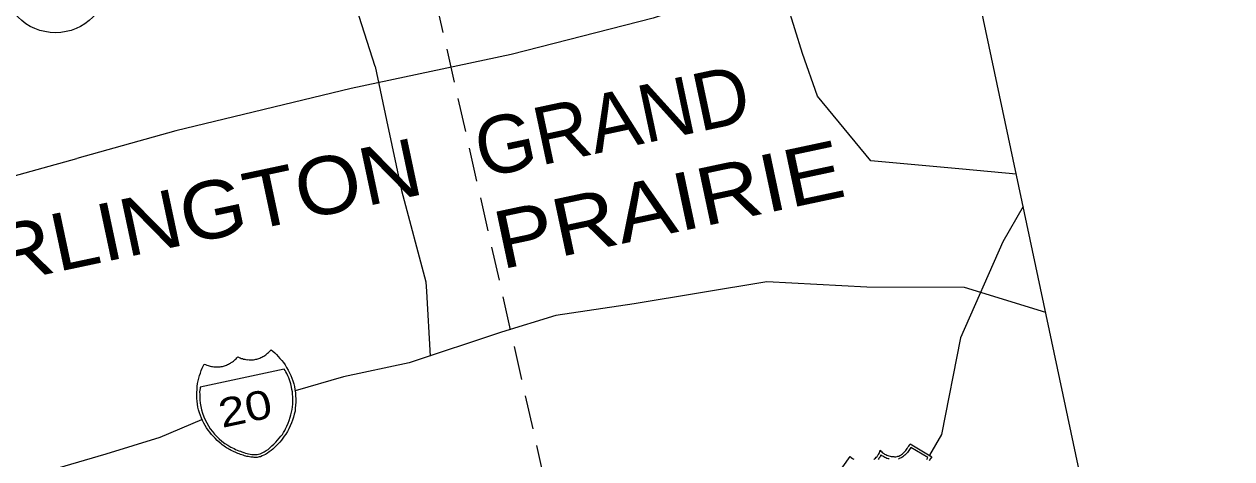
# Model space of a CAD drawing. Extents: x 2357218 to 2371708, y 6973728 to 6980157.
# Drawn here: x 2371493.9 to 2371708, y 6977585.2 to 6977662.2 of the extents above; entities that cross this region are included whole.
import ezdxf

# ---------------------------------------------------------------- set-up
doc = ezdxf.new("R2010")
doc.units = 0
doc.header["$LTSCALE"] = 2
doc.linetypes.add('MEDIUM_DASHED', pattern=[4.5, 3, -1.5])
doc.layers.add('62', color=7, linetype='Continuous', lineweight=13)
doc.layers.add('63', color=7, linetype='Continuous', lineweight=13)

msp = doc.modelspace()

# ---------------------------------------------------------------- linework, layer by layer
at = {"layer": '62', "linetype": 'MEDIUM_DASHED'}
msp.add_line((2371537.006, 6977798.267), (2371599.077, 6977524.204), dxfattribs=at)
at = {"layer": '62'}
for p, q in [((2371556.106, 6977654.73), (2371552.361, 6977666.609)), ((2371565.093, 6977616.567), (2371565.242, 6977614.897)), ((2371565.242, 6977614.897), (2371565.859, 6977603.432)), ((2371656.507, 6977589.526), (2371654.364, 6977585.874))]:
    msp.add_line(p, q, dxfattribs=at)
at = {"layer": '62', "lineweight": 25}
msp.add_line((2371481.196, 6977632.344), (2371503.25, 6977638.459), dxfattribs=at)
for points in [[(2371171.482, 6977817.538), (2371268.218, 6977362.432), (2371707.985, 6977455.907), (2371611.249, 6977911.015)], [(2371659.938, 6977681.952), (2371647.349, 6977677.965), (2371628.369, 6977671.057), (2371605.423, 6977663.305), (2371580.264, 6977656.875), (2371551.849, 6977650.836), (2371520.802, 6977643.338), (2371503.25, 6977638.459)], [(2371674.99, 6977611.147), (2371660.613, 6977615.566), (2371643.295, 6977615.659), (2371625.568, 6977616.583), (2371602.064, 6977612.668), (2371588.144, 6977610.607), (2371578.532, 6977607.666), (2371562.184, 6977602.215), (2371550.54, 6977599.739), (2371541.925, 6977597.309)], [(2371525.33, 6977592.147), (2371517.989, 6977589.024), (2371508.4, 6977586.087), (2371494.884, 6977582.133), (2371485.112, 6977580.058), (2371478.295, 6977577.711), (2371473.995, 6977573.922), (2371464.607, 6977569.925), (2371450.652, 6977568.04), (2371437.897, 6977566.249), (2371423.963, 6977564.162), (2371402.89, 6977556.805), (2371381.813, 6977555.202), (2371364.473, 6977555.496), (2371353.545, 6977558.763), (2371347.781, 6977571.044), (2371345.031, 6977583.983), (2371341.826, 6977589.973), (2371344.749, 6977600.141)]]:
    msp.add_lwpolyline(points, dxfattribs=at)
at = {"layer": '62'}
for points in [[(2371669.776, 6977635.664), (2371660.267, 6977636.565), (2371643.965, 6977638.048), (2371634.547, 6977649.456), (2371631.882, 6977657.01), (2371629.164, 6977665.797), (2371628.025, 6977672.456), (2371627.386, 6977680.002), (2371625.287, 6977686.412), (2371623.525, 6977695.471)], [(2371556.106, 6977654.73), (2371558.125, 6977645.222), (2371560.78, 6977632.741), (2371565.093, 6977616.567)], [(2371670.991, 6977629.94), (2371667.397, 6977623.702), (2371659.911, 6977606.652), (2371656.507, 6977589.526)], [(2371532.597, 6977602.986), (2371532.818, 6977602.918), (2371533.015, 6977602.867), (2371533.203, 6977602.838), (2371533.421, 6977602.793), (2371533.625, 6977602.813), (2371533.797, 6977602.758), (2371534.001, 6977602.777), (2371534.184, 6977602.771), (2371534.391, 6977602.769), (2371534.574, 6977602.786), (2371534.771, 6977602.828), (2371534.969, 6977602.87), (2371535.145, 6977602.907), (2371535.321, 6977602.945), (2371535.514, 6977603.008), (2371535.683, 6977603.09), (2371535.85, 6977603.17), (2371536.043, 6977603.234), (2371536.2, 6977603.359), (2371536.371, 6977603.419), (2371536.55, 6977603.55), (2371536.734, 6977603.658), (2371536.893, 6977603.784), (2371537.044, 6977603.93), (2371537.201, 6977604.056), (2371537.353, 6977604.205), (2371537.546, 6977604.385), (2371537.697, 6977604.53), (2371538.003, 6977604.295), (2371538.337, 6977604.022), (2371538.652, 6977603.722), (2371538.958, 6977603.372), (2371539.261, 6977603.023), (2371539.593, 6977602.654), (2371539.879, 6977602.28), (2371540.177, 6977601.859), (2371540.434, 6977601.408), (2371540.69, 6977600.957), (2371540.952, 6977600.484), (2371541.169, 6977599.999), (2371541.367, 6977599.513), (2371541.532, 6977599.041), (2371541.687, 6977598.546), (2371541.816, 6977598.045), (2371541.909, 6977597.489), (2371541.983, 6977596.928), (2371542.035, 6977596.367), (2371542.075, 6977595.846), (2371542.077, 6977595.294), (2371542.014, 6977594.727), (2371541.967, 6977594.189), (2371541.922, 6977593.65), (2371541.799, 6977593.141), (2371541.639, 6977592.602), (2371541.493, 6977592.088), (2371541.301, 6977591.586), (2371541.092, 6977591.059), (2371540.85, 6977590.571), (2371540.583, 6977590.1), (2371540.274, 6977589.597), (2371540.028, 6977589.244), (2371539.78, 6977588.895), (2371539.512, 6977588.537), (2371539.238, 6977588.203), (2371538.915, 6977587.883), (2371538.596, 6977587.539), (2371538.29, 6977587.243), (2371537.98, 6977586.97), (2371537.672, 6977586.698), (2371537.356, 6977586.447), (2371537.036, 6977586.218), (2371536.684, 6977586.028), (2371536.417, 6977585.878), (2371536.101, 6977585.743), (2371535.829, 6977585.616), (2371535.563, 6977585.559)], [(2371535.563, 6977585.559), (2371535.389, 6977585.522), (2371535.234, 6977585.489), (2371535.029, 6977585.493), (2371534.868, 6977585.481), (2371534.706, 6977585.492), (2371534.493, 6977585.515), (2371534.285, 6977585.519), (2371534.074, 6977585.542), (2371533.858, 6977585.588), (2371533.639, 6977585.634), (2371533.402, 6977585.674), (2371533.207, 6977585.726), (2371532.962, 6977585.789), (2371532.739, 6977585.857), (2371532.521, 6977585.924), (2371532.276, 6977585.987), (2371532.046, 6977586.1), (2371531.796, 6977586.186), (2371531.549, 6977586.27), (2371531.339, 6977586.385), (2371531.113, 6977586.476), (2371530.88, 6977586.61), (2371530.631, 6977586.694), (2371530.443, 6977586.818), (2371530.213, 6977586.93), (2371530.002, 6977587.045), (2371529.769, 6977587.18), (2371529.58, 6977587.323), (2371529.364, 6977587.461), (2371529.177, 6977587.583), (2371529.015, 6977587.711), (2371528.814, 6977587.874), (2371528.456, 6977588.166), (2371528.107, 6977588.505), (2371527.757, 6977588.867), (2371527.454, 6977589.196), (2371527.122, 6977589.562), (2371526.81, 6977589.955), (2371526.522, 6977590.329), (2371526.252, 6977590.734), (2371526.004, 6977591.14), (2371525.753, 6977591.571), (2371525.543, 6977592.009), (2371525.335, 6977592.449), (2371525.144, 6977592.913), (2371524.998, 6977593.388), (2371524.839, 6977593.906), (2371524.712, 6977594.409), (2371524.647, 6977594.924), (2371524.585, 6977595.44), (2371524.527, 6977595.933), (2371524.529, 6977596.463), (2371524.533, 6977596.994), (2371524.554, 6977597.526), (2371524.606, 6977598.044), (2371524.658, 6977598.56), (2371524.757, 6977599.065), (2371524.866, 6977599.524), (2371524.998, 6977599.991), (2371525.156, 6977600.438), (2371525.312, 6977600.886), (2371525.461, 6977601.285), (2371525.655, 6977601.67), (2371525.836, 6977602.008), (2371526.057, 6977601.941), (2371526.285, 6977601.852), (2371526.504, 6977601.782), (2371526.679, 6977601.728), (2371526.898, 6977601.658), (2371527.093, 6977601.608), (2371527.304, 6977601.585), (2371527.523, 6977601.54), (2371527.704, 6977601.554), (2371527.898, 6977601.504), (2371528.102, 6977601.525), (2371528.286, 6977601.518), (2371528.491, 6977601.515), (2371528.674, 6977601.532), (2371528.852, 6977601.57), (2371529.071, 6977601.614), (2371529.223, 6977601.649), (2371529.423, 6977601.689), (2371529.595, 6977601.748), (2371529.783, 6977601.836), (2371529.952, 6977601.916), (2371530.123, 6977601.977), (2371530.302, 6977602.106), (2371530.492, 6977602.171), (2371530.628, 6977602.292), (2371530.814, 6977602.399), (2371530.993, 6977602.529), (2371531.169, 6977602.683), (2371531.303, 6977602.803), (2371531.477, 6977602.954), (2371531.625, 6977603.123), (2371531.801, 6977603.277), (2371531.999, 6977603.204), (2371532.179, 6977603.103), (2371532.404, 6977603.037), (2371532.597, 6977602.986)], [(2371644.497, 6977585.11), (2371644.654, 6977585.234), (2371644.812, 6977585.36), (2371644.96, 6977585.529), (2371645.091, 6977585.672), (2371645.212, 6977585.861), (2371645.346, 6977585.981), (2371645.442, 6977586.186), (2371645.519, 6977586.363), (2371645.569, 6977586.557), (2371645.62, 6977586.753), (2371645.767, 6977586.599), (2371645.939, 6977586.452), (2371646.084, 6977586.299), (2371646.271, 6977586.178), (2371646.435, 6977586.051), (2371646.635, 6977585.977), (2371646.818, 6977585.878), (2371647.017, 6977585.807), (2371647.212, 6977585.754), (2371647.411, 6977585.682), (2371647.623, 6977585.658), (2371647.813, 6977585.63), (2371648.043, 6977585.635), (2371648.212, 6977585.599), (2371648.441, 6977585.603), (2371648.638, 6977585.645), (2371648.793, 6977585.677), (2371648.969, 6977585.715), (2371649.107, 6977585.813), (2371649.298, 6977585.899), (2371649.433, 6977586.02), (2371649.595, 6977586.125), (2371649.727, 6977586.266), (2371649.884, 6977586.392), (2371650.01, 6977586.557), (2371650.18, 6977586.731), (2371650.305, 6977586.895), (2371650.454, 6977587.065), (2371650.57, 6977587.274), (2371650.734, 6977587.471), (2371650.832, 6977587.676), (2371650.969, 6977587.888), (2371654.786, 6977585.616), (2371654.561, 6977585.273), (2371654.346, 6977584.881)], [(2371653.923, 6977585.136), (2371654.08, 6977585.468), (2371651.078, 6977587.267), (2371650.956, 6977587.082), (2371650.856, 6977586.897), (2371650.741, 6977586.689), (2371650.616, 6977586.525), (2371650.467, 6977586.354), (2371650.318, 6977586.187), (2371650.168, 6977586.038), (2371650.013, 6977585.892), (2371649.834, 6977585.762), (2371649.681, 6977585.615), (2371649.5, 6977585.484), (2371649.357, 6977585.407), (2371649.169, 6977585.322), (2371649.019, 6977585.266), (2371648.895, 6977585.194)], [(2371637.751, 6977581.997), (2371640.317, 6977585.624), (2371640.535, 6977585.464), (2371640.753, 6977585.302), (2371640.983, 6977585.191)], [(2371647.236, 6977585.21), (2371647.067, 6977585.243), (2371646.825, 6977585.306), (2371646.669, 6977585.387), (2371646.492, 6977585.466), (2371646.289, 6977585.558), (2371646.144, 6977585.689), (2371645.964, 6977585.79), (2371645.79, 6977585.96), (2371645.695, 6977585.756), (2371645.618, 6977585.577), (2371645.491, 6977585.413), (2371645.382, 6977585.275), (2371645.272, 6977585.136)]]:
    msp.add_lwpolyline(points, dxfattribs=at)
msp.add_lwpolyline([(2371540.018, 6977601.089), (2371525.116, 6977597.923), (2371525.097, 6977597.687), (2371525.041, 6977597.4), (2371525.018, 6977597.074), (2371525.043, 6977596.642), (2371525.022, 6977596.2), (2371525.042, 6977595.676), (2371525.114, 6977595.115), (2371525.219, 6977594.516), (2371525.371, 6977593.904), (2371525.545, 6977593.298), (2371525.764, 6977592.701), (2371525.997, 6977592.152), (2371526.276, 6977591.59), (2371526.569, 6977591.078), (2371526.912, 6977590.552), (2371527.267, 6977590.076), (2371527.64, 6977589.627), (2371528.062, 6977589.162), (2371528.493, 6977588.748), (2371528.972, 6977588.346), (2371529.487, 6977587.97), (2371529.992, 6977587.642), (2371530.545, 6977587.322), (2371531.108, 6977587.049), (2371531.375, 6977586.877), (2371531.67, 6977586.778), (2371531.95, 6977586.655), (2371532.27, 6977586.562), (2371532.523, 6977586.452), (2371532.824, 6977586.335), (2371533.118, 6977586.259), (2371533.43, 6977586.187), (2371533.696, 6977586.129), (2371533.983, 6977586.075), (2371534.273, 6977586.021), (2371534.506, 6977586.001), (2371534.76, 6977585.988), (2371534.991, 6977585.989), (2371535.243, 6977585.998), (2371535.462, 6977586.043), (2371535.766, 6977586.132), (2371536.126, 6977586.278), (2371536.429, 6977586.479), (2371536.817, 6977586.701), (2371537.167, 6977586.912), (2371537.493, 6977587.213), (2371537.842, 6977587.516), (2371538.188, 6977587.841), (2371538.527, 6977588.191), (2371538.825, 6977588.53), (2371539.119, 6977588.869), (2371539.41, 6977589.228), (2371539.685, 6977589.562), (2371539.888, 6977589.906), (2371540.098, 6977590.226), (2371540.237, 6977590.533), (2371540.474, 6977591.043), (2371540.683, 6977591.571), (2371540.882, 6977592.05), (2371541.043, 6977592.59), (2371541.173, 6977593.055), (2371541.282, 6977593.515), (2371541.393, 6977593.975), (2371541.452, 6977594.448), (2371541.512, 6977594.923), (2371541.561, 6977595.347), (2371541.556, 6977595.805), (2371541.532, 6977596.235), (2371541.488, 6977596.663), (2371541.465, 6977597.096), (2371541.377, 6977597.513), (2371541.309, 6977597.936), (2371541.161, 6977598.526), (2371541.001, 6977599.068), (2371540.825, 6977599.559), (2371540.672, 6977599.964), (2371540.472, 6977600.357), (2371540.296, 6977600.643), (2371540.152, 6977600.887)], close=True, dxfattribs=at)
msp.add_circle((2371499.456, 6977670.084), 9.364, dxfattribs=at)
at = {"layer": '63', "linetype": 'MEDIUM_DASHED'}
msp.add_line((2371537.006, 6977798.267), (2371599.077, 6977524.204), dxfattribs=at)
at = {"layer": '63'}
for p, q in [((2371556.106, 6977654.73), (2371552.361, 6977666.609)), ((2371565.093, 6977616.567), (2371565.242, 6977614.897)), ((2371565.242, 6977614.897), (2371565.859, 6977603.432)), ((2371656.507, 6977589.526), (2371654.364, 6977585.874))]:
    msp.add_line(p, q, dxfattribs=at)
at = {"layer": '63', "lineweight": 25}
msp.add_line((2371481.196, 6977632.344), (2371503.25, 6977638.459), dxfattribs=at)
for points in [[(2371171.482, 6977817.538), (2371268.218, 6977362.432), (2371707.985, 6977455.907), (2371611.249, 6977911.015)], [(2371659.938, 6977681.952), (2371647.349, 6977677.965), (2371628.369, 6977671.057), (2371605.423, 6977663.305), (2371580.264, 6977656.875), (2371551.849, 6977650.836), (2371520.802, 6977643.338), (2371503.25, 6977638.459)], [(2371674.99, 6977611.147), (2371660.613, 6977615.566), (2371643.295, 6977615.659), (2371625.568, 6977616.583), (2371602.064, 6977612.668), (2371588.144, 6977610.607), (2371578.532, 6977607.666), (2371562.184, 6977602.215), (2371550.54, 6977599.739), (2371541.925, 6977597.309)], [(2371525.33, 6977592.147), (2371517.989, 6977589.024), (2371508.4, 6977586.087), (2371494.884, 6977582.133), (2371485.112, 6977580.058), (2371478.295, 6977577.711), (2371473.995, 6977573.922), (2371464.607, 6977569.925), (2371450.652, 6977568.04), (2371437.897, 6977566.249), (2371423.963, 6977564.162), (2371402.89, 6977556.805), (2371381.813, 6977555.202), (2371364.473, 6977555.496), (2371353.545, 6977558.763), (2371347.781, 6977571.044), (2371345.031, 6977583.983), (2371341.826, 6977589.973), (2371344.749, 6977600.141)]]:
    msp.add_lwpolyline(points, dxfattribs=at)
at = {"layer": '63'}
for points in [[(2371669.776, 6977635.664), (2371660.267, 6977636.565), (2371643.965, 6977638.048), (2371634.547, 6977649.456), (2371631.882, 6977657.01), (2371629.164, 6977665.797), (2371628.025, 6977672.456), (2371627.386, 6977680.002), (2371625.287, 6977686.412), (2371623.525, 6977695.471)], [(2371556.106, 6977654.73), (2371558.125, 6977645.222), (2371560.78, 6977632.741), (2371565.093, 6977616.567)], [(2371670.991, 6977629.94), (2371667.397, 6977623.702), (2371659.911, 6977606.652), (2371656.507, 6977589.526)], [(2371532.597, 6977602.986), (2371532.818, 6977602.918), (2371533.015, 6977602.867), (2371533.203, 6977602.838), (2371533.421, 6977602.793), (2371533.625, 6977602.813), (2371533.797, 6977602.758), (2371534.001, 6977602.777), (2371534.184, 6977602.771), (2371534.391, 6977602.769), (2371534.574, 6977602.786), (2371534.771, 6977602.828), (2371534.969, 6977602.87), (2371535.145, 6977602.907), (2371535.321, 6977602.945), (2371535.514, 6977603.008), (2371535.683, 6977603.09), (2371535.85, 6977603.17), (2371536.043, 6977603.234), (2371536.2, 6977603.359), (2371536.371, 6977603.419), (2371536.55, 6977603.55), (2371536.734, 6977603.658), (2371536.893, 6977603.784), (2371537.044, 6977603.93), (2371537.201, 6977604.056), (2371537.353, 6977604.205), (2371537.546, 6977604.385), (2371537.697, 6977604.53), (2371538.003, 6977604.295), (2371538.337, 6977604.022), (2371538.652, 6977603.722), (2371538.958, 6977603.372), (2371539.261, 6977603.023), (2371539.593, 6977602.654), (2371539.879, 6977602.28), (2371540.177, 6977601.859), (2371540.434, 6977601.408), (2371540.69, 6977600.957), (2371540.952, 6977600.484), (2371541.169, 6977599.999), (2371541.367, 6977599.513), (2371541.532, 6977599.041), (2371541.687, 6977598.546), (2371541.816, 6977598.045), (2371541.909, 6977597.489), (2371541.983, 6977596.928), (2371542.035, 6977596.367), (2371542.075, 6977595.846), (2371542.077, 6977595.294), (2371542.014, 6977594.727), (2371541.967, 6977594.189), (2371541.922, 6977593.65), (2371541.799, 6977593.141), (2371541.639, 6977592.602), (2371541.493, 6977592.088), (2371541.301, 6977591.586), (2371541.092, 6977591.059), (2371540.85, 6977590.571), (2371540.583, 6977590.1), (2371540.274, 6977589.597), (2371540.028, 6977589.244), (2371539.78, 6977588.895), (2371539.512, 6977588.537), (2371539.238, 6977588.203), (2371538.915, 6977587.883), (2371538.596, 6977587.539), (2371538.29, 6977587.243), (2371537.98, 6977586.97), (2371537.672, 6977586.698), (2371537.356, 6977586.447), (2371537.036, 6977586.218), (2371536.684, 6977586.028), (2371536.417, 6977585.878), (2371536.101, 6977585.743), (2371535.829, 6977585.616), (2371535.563, 6977585.559)], [(2371535.563, 6977585.559), (2371535.389, 6977585.522), (2371535.234, 6977585.489), (2371535.029, 6977585.493), (2371534.868, 6977585.481), (2371534.706, 6977585.492), (2371534.493, 6977585.515), (2371534.285, 6977585.519), (2371534.074, 6977585.542), (2371533.858, 6977585.588), (2371533.639, 6977585.634), (2371533.402, 6977585.674), (2371533.207, 6977585.726), (2371532.962, 6977585.789), (2371532.739, 6977585.857), (2371532.521, 6977585.924), (2371532.276, 6977585.987), (2371532.046, 6977586.1), (2371531.796, 6977586.186), (2371531.549, 6977586.27), (2371531.339, 6977586.385), (2371531.113, 6977586.476), (2371530.88, 6977586.61), (2371530.631, 6977586.694), (2371530.443, 6977586.818), (2371530.213, 6977586.93), (2371530.002, 6977587.045), (2371529.769, 6977587.18), (2371529.58, 6977587.323), (2371529.364, 6977587.461), (2371529.177, 6977587.583), (2371529.015, 6977587.711), (2371528.814, 6977587.874), (2371528.456, 6977588.166), (2371528.107, 6977588.505), (2371527.757, 6977588.867), (2371527.454, 6977589.196), (2371527.122, 6977589.562), (2371526.81, 6977589.955), (2371526.522, 6977590.329), (2371526.252, 6977590.734), (2371526.004, 6977591.14), (2371525.753, 6977591.571), (2371525.543, 6977592.009), (2371525.335, 6977592.449), (2371525.144, 6977592.913), (2371524.998, 6977593.388), (2371524.839, 6977593.906), (2371524.712, 6977594.409), (2371524.647, 6977594.924), (2371524.585, 6977595.44), (2371524.527, 6977595.933), (2371524.529, 6977596.463), (2371524.533, 6977596.994), (2371524.554, 6977597.526), (2371524.606, 6977598.044), (2371524.658, 6977598.56), (2371524.757, 6977599.065), (2371524.866, 6977599.524), (2371524.998, 6977599.991), (2371525.156, 6977600.438), (2371525.312, 6977600.886), (2371525.461, 6977601.285), (2371525.655, 6977601.67), (2371525.836, 6977602.008), (2371526.057, 6977601.941), (2371526.285, 6977601.852), (2371526.504, 6977601.782), (2371526.679, 6977601.728), (2371526.898, 6977601.658), (2371527.093, 6977601.608), (2371527.304, 6977601.585), (2371527.523, 6977601.54), (2371527.704, 6977601.554), (2371527.898, 6977601.504), (2371528.102, 6977601.525), (2371528.286, 6977601.518), (2371528.491, 6977601.515), (2371528.674, 6977601.532), (2371528.852, 6977601.57), (2371529.071, 6977601.614), (2371529.223, 6977601.649), (2371529.423, 6977601.689), (2371529.595, 6977601.748), (2371529.783, 6977601.836), (2371529.952, 6977601.916), (2371530.123, 6977601.977), (2371530.302, 6977602.106), (2371530.492, 6977602.171), (2371530.628, 6977602.292), (2371530.814, 6977602.399), (2371530.993, 6977602.529), (2371531.169, 6977602.683), (2371531.303, 6977602.803), (2371531.477, 6977602.954), (2371531.625, 6977603.123), (2371531.801, 6977603.277), (2371531.999, 6977603.204), (2371532.179, 6977603.103), (2371532.404, 6977603.037), (2371532.597, 6977602.986)], [(2371644.497, 6977585.11), (2371644.654, 6977585.234), (2371644.812, 6977585.36), (2371644.96, 6977585.529), (2371645.091, 6977585.672), (2371645.212, 6977585.861), (2371645.346, 6977585.981), (2371645.442, 6977586.186), (2371645.519, 6977586.363), (2371645.569, 6977586.557), (2371645.62, 6977586.753), (2371645.767, 6977586.599), (2371645.939, 6977586.452), (2371646.084, 6977586.299), (2371646.271, 6977586.178), (2371646.435, 6977586.051), (2371646.635, 6977585.977), (2371646.818, 6977585.878), (2371647.017, 6977585.807), (2371647.212, 6977585.754), (2371647.411, 6977585.682), (2371647.623, 6977585.658), (2371647.813, 6977585.63), (2371648.043, 6977585.635), (2371648.212, 6977585.599), (2371648.441, 6977585.603), (2371648.638, 6977585.645), (2371648.793, 6977585.677), (2371648.969, 6977585.715), (2371649.107, 6977585.813), (2371649.298, 6977585.899), (2371649.433, 6977586.02), (2371649.595, 6977586.125), (2371649.727, 6977586.266), (2371649.884, 6977586.392), (2371650.01, 6977586.557), (2371650.18, 6977586.731), (2371650.305, 6977586.895), (2371650.454, 6977587.065), (2371650.57, 6977587.274), (2371650.734, 6977587.471), (2371650.832, 6977587.676), (2371650.969, 6977587.888), (2371654.786, 6977585.616), (2371654.561, 6977585.273), (2371654.346, 6977584.881)], [(2371653.923, 6977585.136), (2371654.08, 6977585.468), (2371651.078, 6977587.267), (2371650.956, 6977587.082), (2371650.856, 6977586.897), (2371650.741, 6977586.689), (2371650.616, 6977586.525), (2371650.467, 6977586.354), (2371650.318, 6977586.187), (2371650.168, 6977586.038), (2371650.013, 6977585.892), (2371649.834, 6977585.762), (2371649.681, 6977585.615), (2371649.5, 6977585.484), (2371649.357, 6977585.407), (2371649.169, 6977585.322), (2371649.019, 6977585.266), (2371648.895, 6977585.194)], [(2371637.751, 6977581.997), (2371640.317, 6977585.624), (2371640.535, 6977585.464), (2371640.753, 6977585.302), (2371640.983, 6977585.191)], [(2371647.236, 6977585.21), (2371647.067, 6977585.243), (2371646.825, 6977585.306), (2371646.669, 6977585.387), (2371646.492, 6977585.466), (2371646.289, 6977585.558), (2371646.144, 6977585.689), (2371645.964, 6977585.79), (2371645.79, 6977585.96), (2371645.695, 6977585.756), (2371645.618, 6977585.577), (2371645.491, 6977585.413), (2371645.382, 6977585.275), (2371645.272, 6977585.136)]]:
    msp.add_lwpolyline(points, dxfattribs=at)
msp.add_lwpolyline([(2371540.018, 6977601.089), (2371525.116, 6977597.923), (2371525.097, 6977597.687), (2371525.041, 6977597.4), (2371525.018, 6977597.074), (2371525.043, 6977596.642), (2371525.022, 6977596.2), (2371525.042, 6977595.676), (2371525.114, 6977595.115), (2371525.219, 6977594.516), (2371525.371, 6977593.904), (2371525.545, 6977593.298), (2371525.764, 6977592.701), (2371525.997, 6977592.152), (2371526.276, 6977591.59), (2371526.569, 6977591.078), (2371526.912, 6977590.552), (2371527.267, 6977590.076), (2371527.64, 6977589.627), (2371528.062, 6977589.162), (2371528.493, 6977588.748), (2371528.972, 6977588.346), (2371529.487, 6977587.97), (2371529.992, 6977587.642), (2371530.545, 6977587.322), (2371531.108, 6977587.049), (2371531.375, 6977586.877), (2371531.67, 6977586.778), (2371531.95, 6977586.655), (2371532.27, 6977586.562), (2371532.523, 6977586.452), (2371532.824, 6977586.335), (2371533.118, 6977586.259), (2371533.43, 6977586.187), (2371533.696, 6977586.129), (2371533.983, 6977586.075), (2371534.273, 6977586.021), (2371534.506, 6977586.001), (2371534.76, 6977585.988), (2371534.991, 6977585.989), (2371535.243, 6977585.998), (2371535.462, 6977586.043), (2371535.766, 6977586.132), (2371536.126, 6977586.278), (2371536.429, 6977586.479), (2371536.817, 6977586.701), (2371537.167, 6977586.912), (2371537.493, 6977587.213), (2371537.842, 6977587.516), (2371538.188, 6977587.841), (2371538.527, 6977588.191), (2371538.825, 6977588.53), (2371539.119, 6977588.869), (2371539.41, 6977589.228), (2371539.685, 6977589.562), (2371539.888, 6977589.906), (2371540.098, 6977590.226), (2371540.237, 6977590.533), (2371540.474, 6977591.043), (2371540.683, 6977591.571), (2371540.882, 6977592.05), (2371541.043, 6977592.59), (2371541.173, 6977593.055), (2371541.282, 6977593.515), (2371541.393, 6977593.975), (2371541.452, 6977594.448), (2371541.512, 6977594.923), (2371541.561, 6977595.347), (2371541.556, 6977595.805), (2371541.532, 6977596.235), (2371541.488, 6977596.663), (2371541.465, 6977597.096), (2371541.377, 6977597.513), (2371541.309, 6977597.936), (2371541.161, 6977598.526), (2371541.001, 6977599.068), (2371540.825, 6977599.559), (2371540.672, 6977599.964), (2371540.472, 6977600.357), (2371540.296, 6977600.643), (2371540.152, 6977600.887)], close=True, dxfattribs=at)
msp.add_circle((2371499.456, 6977670.084), 9.364, dxfattribs=at)

# ---------------------------------------------------------------- texts
at = {"layer": '62'}
msp.add_text('GRAND', height=10.21, rotation=12, dxfattribs=at).set_placement((2371575.053, 6977634.97))
for s, height, width, p in [('ARLINGTON', 10.21, 1.1, (2371479.417, 6977613.998)), ('PRAIRIE', 10.21, 1.15, (2371578.496, 6977618.772)), ('20', 5.099, 1.25, (2371528.978, 6977590.693))]:
    msp.add_text(s, height=height, rotation=12, dxfattribs=dict(at, width=width)).set_placement(p)
at = {"layer": '63'}
msp.add_text('GRAND', height=10.21, rotation=12, dxfattribs=at).set_placement((2371575.053, 6977634.97))
for s, height, width, p in [('ARLINGTON', 10.21, 1.1, (2371479.417, 6977613.998)), ('PRAIRIE', 10.21, 1.15, (2371578.496, 6977618.772)), ('20', 5.099, 1.25, (2371528.978, 6977590.693))]:
    msp.add_text(s, height=height, rotation=12, dxfattribs=dict(at, width=width)).set_placement(p)

doc.saveas('drawing.dxf')
